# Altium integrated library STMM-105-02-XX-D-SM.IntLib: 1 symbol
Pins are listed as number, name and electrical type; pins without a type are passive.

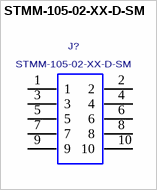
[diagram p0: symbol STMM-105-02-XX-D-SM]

## STMM-105-02-XX-D-SM
designator J?
2 MM TERMINAL STRIP ASSEMBLY, 10 PINS.; MANUFACTURER: SAMTEC
footprint STMM-105-02-XX-D-SM
pins: 1, 2, 3, 4, 5, 6, 7, 8, 9, 10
